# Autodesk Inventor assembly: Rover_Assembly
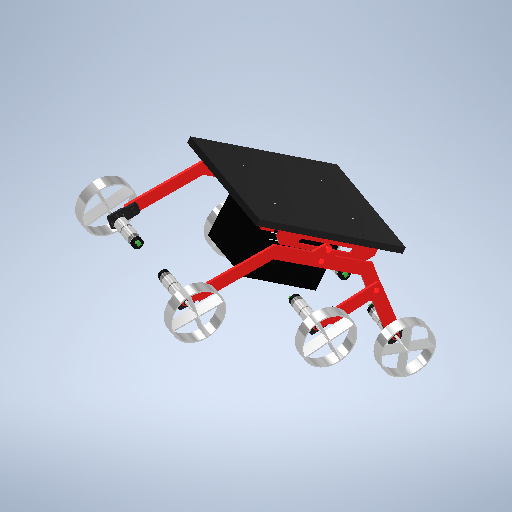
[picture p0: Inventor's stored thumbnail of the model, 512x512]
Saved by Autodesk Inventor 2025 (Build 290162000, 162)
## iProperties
Created: 2024-09
Part Number: Rover_Assembly
Document SubType Name: Assembly
Designer: aryas
Author: aryas
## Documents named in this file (2)
- C:\Users\aryas\Documents\Rover\Rover_Assembly.iam
- C:\Users\aryas\Downloads\rover-8.snapshot.11\rover\rover.iam
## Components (1 placed, 1 different names)
1. rover:1 [sub-assembly]
